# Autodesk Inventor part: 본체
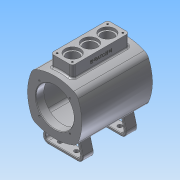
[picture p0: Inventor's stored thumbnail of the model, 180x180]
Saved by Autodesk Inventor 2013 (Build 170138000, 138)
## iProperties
Created: 2015-11
Part Number: 본체
Material: 알루미늄 6061
Document SubType Name: Modeling
Designer: mduedu
Density: 2.71 g/cm^3
Mass: 1109.75 g
Surface Area: 1165.94 cm^2
Volume: 409.503 cm^3
Author: mduedu
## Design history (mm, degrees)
sketch "스케치2"
  geometry: L1 (0, 250)-(0, -250); L2 (250, 0)-(-250, 0); L3 (-50, 50)-(50, 50); L4 (50, 50)-(50, -50); L5 (50, -50)-(-50, -50); L6 (-50, -50)-(-50, 50); A1 r 90 centre (-40, 0) between (40.415, -40.415) and (40.415, 40.415); A2 r 90 centre (40, 0) between (-40.415, 40.415) and (-40.415, -40.415); A3 r 90 centre (0, -40) between (40.415, 40.415) and (-40.415, 40.415); A4 r 90 centre (0, 40) between (-40.415, -40.415) and (40.415, -40.415); 2 further points
  constraints: 12 end point, 8 point on circle, 4 centre point, 4 tangent, 3 perpendicular, 2 horizontal alignment, 2 midpoint, 2 parallel, 2 symmetric about line, 1 coincident, 1 equal radius, 1 horizontal, 1 vertical, 1 vertical alignment, 2 other
  dimensions: "d6" = 500 distance of L1.start L1.end; "d8" = 500 distance of L2.start L2.end; "d9" = 100 distance of L3.end L4.end; "d11" = 90 radius of A3
extrude "돌출1" new body sketch "스케치2" stored distance "d12" = 130; taper "d13" = 0 deg
fillet "모깎기6" dims "d30" = 15
feature "쉘1" dims "d31" = 15, "d32" = 6, "d33" = 15
sketch "스케치5"
  geometry: C1 r 35 at (0, 0); 1 further point
  constraints: 1 centre point, 1 coincident
  dimensions: "d34" = 70 diameter of C1
extrude "돌출3" cut sketch "스케치5" stored distance "d36" = 3; taper "d37" = 0 deg
fillet "모깎기14" dims "d78" = 3
sketch "스케치12"
  geometry: L1 (0, 0)-(28.284, 28.284); L2 (0, 0)-(40, 0); A1 r 40 centre (0, 0) between (28.284, 28.284) and (40, 0); 2 further points
  constraints: 4 end point, 2 coincident, 2 point on circle, 1 centre point, 1 horizontal
  dimensions: "d79" = 80 diameter of A1; "d80" = 45 deg angle of L2 L1
hole "구멍2" sketch "스케치12" at (28.284, 28.284) diameter "d82" = 3.242; stored, may be unused: countersink angle "d86" = 90 deg, drill point angle "d88" = 118 deg; dims "d83" = 9, "d84" = 10, "d85" = 2, "d87" = 11
node "작업 평면2"
sketch "스케치13"
  geometry: L1 (-52.5, -20)-(52.5, -20); L2 (52.5, -20)-(52.5, 20); L3 (52.5, 20)-(-52.5, 20); L4 (-52.5, 20)-(-52.5, -20); L5 (-52.5, -20)-(52.5, 20); L6 (52.5, -20)-(-52.5, 20); 1 further point
  constraints: 12 end point, 2 midpoint, 2 parallel, 1 horizontal, 1 perpendicular
  dimensions: "d93" = 105 distance of L2.end L3.end; "d95" = 40 distance of L1.end L2.end
extrude "돌출8" join sketch "스케치13" stored distance "d96" = 80; taper "d97" = 0 deg
fillet "모깎기15" dims "d98" = 5
fillet "모깎기16" dims "d99" = 3
sketch "스케치14"
  geometry: L1 (-52.5, 15)-(-52.5, -15) reference; L2 (52.5, -15)-(52.5, 15) reference; L3 (-52.5, 0)-(52.5, 0); 4 further points
  constraints: 2 end point, 2 midpoint, 2 point on line, 1 coincident
  dimensions: "d100" = 32 distance of point (-32, 0) point (0, 0); "d102" = 32 distance of point (32, 0) point (0, 0) (derived)
hole "구멍3" sketch "스케치14" at (-32, 0), (0, 0), (32, 0) diameter "d103" = 22; stored, may be unused: countersink angle "d107" = 90 deg, drill point angle "d109" = 118 deg; dims "d104" = 8, "d105" = 28, "d106" = 5, "d108" = 10
sketch "스케치15"
  geometry: L1 (46.5, -14)-(-46.5, -14); L2 (-46.5, -14)-(-46.5, 14); L3 (-46.5, 14)-(46.5, 14); L4 (46.5, 14)-(46.5, -14); L5 (46.5, -14)-(-46.5, 14); L6 (-46.5, -14)-(46.5, 14); L7 (47.5, 20)-(-47.5, 20) reference; L8 (-52.5, 15)-(-52.5, -15) reference; 5 further points
  constraints: 12 end point, 4 coincident, 2 midpoint, 2 parallel, 1 horizontal, 1 perpendicular
  dimensions: "d110" = 6 distance between parallel lines of L3 L7; "d111" = 6 distance between parallel lines of L2 L8
hole "구멍4" sketch "스케치15" at (-46.5, 14), (46.5, 14), (46.5, -14), (-46.5, -14) diameter "d112" = 3.242; stored, may be unused: countersink angle "d116" = 90 deg, drill point angle "d118" = 118 deg; dims "d113" = 10, "d114" = 28, "d115" = 5, "d117" = 13
sketch "스케치16"
  geometry: L1 (33.5, 0)-(61.5, 0) reference; 2 further points
  constraints: 1 vertical alignment, 1 other
  dimensions: "d128" = 11 distance from line of L1 point (47.5, -11)
feature "엠보싱2" sketch "스케치16" dims "d6" = 500, "d8" = 500, "d9" = 100, "d11" = 90, "d34" = 70, "d123" = 0.5, "d124" = 0
chamfer "모따기1" distance "d125" = 1; stored, may be unused: second distance "d126" = 2, angle "d127" = 45 deg
sketch "스케치18"
  geometry: L1 (0, 0)-(0, -80); L2 (40, -80)-(30.531, -44.663); L3 (-40, -80)-(-30.531, -44.663); L4 (-40, -80)-(40, -80); A1 r 90 centre (0, 40) between (-34.941, -42.941) and (34.941, -42.941) reference; A2 r 90 centre (0, 40) between (-30.531, -44.663) and (30.531, -44.663)
  constraints: 8 end point, 3 point on circle, 2 symmetric about line, 1 centre point, 1 coincident, 1 midpoint, 1 perpendicular, 1 vertical
  dimensions: "d132" = 80 distance of L3.start L2.start; "d134" = 75 deg angle of L4 L2; "d136" = 80 distance of L1.start L1.end
extrude "돌출9" new body sketch "스케치18" stored distance "d137" = 100; taper "d138" = 0 deg
fillet "모깎기17" dims "d139" = 10
sketch "스케치19"
  geometry: L1 (26.968, -80)-(-26.968, -80) reference; L2 (-36.627, -67.412)-(-30.531, -44.663) reference; L3 (30.531, -44.663)-(36.627, -67.412) reference; L4 (-25.775, -46.23)-(-31.797, -68.706); L5 (-26.968, -75)-(26.968, -75); L6 (31.797, -68.706)-(25.775, -46.23); L7 (0, 0)-(0, -80); A1 r 10 centre (26.968, -70) between (26.968, -80) and (36.627, -67.412) reference; A2 r 10 centre (-26.968, -70) between (-36.627, -67.412) and (-26.968, -80) reference; A3 r 90 centre (0, 40) between (-30.531, -44.663) and (30.531, -44.663) reference; A4 r 5 centre (-26.968, -70) between (-31.797, -68.706) and (-26.968, -75); A5 r 5 centre (26.968, -70) between (26.968, -75) and (31.797, -68.706); A6 r 90 centre (0, 40) between (-25.775, -46.23) and (25.775, -46.23)
  constraints: 8 end point, 7 point on circle, 3 centre point, 2 parallel, 1 coincident, 1 midpoint, 1 symmetric about line, 1 tangent, 2 other
  dimensions: "d140" = 5 distance between parallel lines of L1 L5
extrude "돌출10" cut sketch "스케치19" stored distance "d141" = 100; taper "d142" = 0 deg
sketch "스케치20"
  geometry: L1 (-30, 0)-(30, 0); L2 (30, 0)-(30, -90); L3 (30, -90)-(-30, -90); L4 (-30, -90)-(-30, 0); L5 (50, -80)-(-50, -80) reference; 2 further points
  constraints: 8 end point, 2 parallel, 1 coincident, 1 horizontal, 1 midpoint, 1 perpendicular
  dimensions: "d143" = 10 distance from line of L5 L2.end; "d144" = 60 distance of L2.end L3.end
extrude "돌출11" cut sketch "스케치20" stored distance "d145" = 100; taper "d146" = 0 deg
sketch "스케치21"
  geometry: L1 (0, 26.968)-(100, 26.968); L2 (100, 53.935)-(100, 0) reference; L3 (0, 0)-(0, 53.935) reference; L4 (0, 53.935)-(20, 53.935) reference; L5 (20, 0)-(0, 0) reference; L6 (115, 76.968)-(-15, 76.968) reference; L7 (115, -23.032)-(-15, -23.032) reference; L8 (10, 53.935)-(10, 0); L9 (50, 76.968)-(50, -23.032); C1 r 4 at (10, 41.968); C2 r 4 at (10, 11.968); C3 r 4 at (90, 41.968); C4 r 4 at (90, 11.968); 2 further points
  constraints: 6 end point, 6 midpoint, 4 centre point, 3 symmetric about line, 1 coincident, 1 horizontal, 1 point on line, 3 other
  dimensions: "d147" = 8 diameter of C1; "d148" = 15 distance from line of C1.centre L1
extrude "돌출12" cut sketch "스케치21" stored distance "d149" = 100; taper "d150" = 0 deg
feature "결합2"
  node "솔리드3"
fillet "모깎기18" dims "d151" = 1
fillet "모깎기19" dims "d152" = 2
node "솔리드1"
pattern_circular "원형 패턴1" dims angle "d90" = 360 deg
mirror "대칭3"
node "투영된 루프1"
